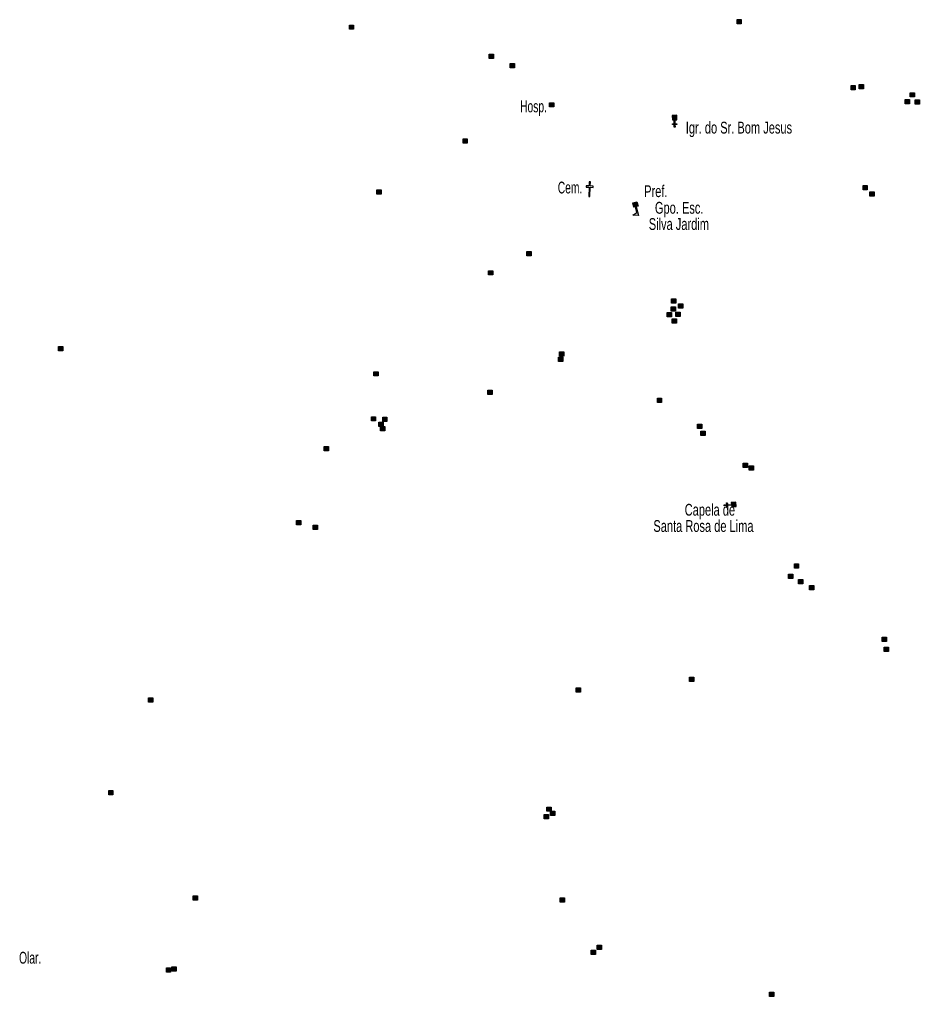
# Model space of a CAD drawing. Extents: x 647.8 to 672.9, y 6929.3 to 6957.3.
# Drawn here: x 660.13 to 666.23, y 6929.5 to 6936.12 of the extents above; entities that cross this region are included whole.
import ezdxf
from ezdxf.enums import TextEntityAlignment as Align

# ---------------------------------------------------------------- set-up
doc = ezdxf.new("R2010")
doc.units = 0
doc.header["$LTSCALE"] = 0.032
for name, color, linetype, lineweight in [('2', 7, 'Continuous', 25), ('20', 7, 'Continuous', 25), ('4', 7, 'Continuous', 25), ('6', 7, 'Continuous', 25)]:
    doc.layers.add(name, color=color, linetype=linetype, lineweight=lineweight)
doc.layers.add('61', color=7, linetype='Continuous')

msp = doc.modelspace()

# ---------------------------------------------------------------- hatches: boundary and pattern name
at = {"layer": '2'}
for points in [[(664.9931, 6936.1187), (665.0221, 6936.1187), (665.0221, 6936.0897), (664.9931, 6936.0897)], [(662.367, 6936.0814), (662.396, 6936.0814), (662.396, 6936.0524), (662.367, 6936.0524)], [(663.3148, 6935.884), (663.3438, 6935.884), (663.3438, 6935.855), (663.3148, 6935.855)], [(663.4574, 6935.8204), (663.4864, 6935.8204), (663.4864, 6935.7914), (663.4574, 6935.7914)], [(665.7653, 6935.6712), (665.7943, 6935.6712), (665.7943, 6935.6422), (665.7653, 6935.6422)], [(665.8201, 6935.6778), (665.8491, 6935.6778), (665.8491, 6935.6488), (665.8201, 6935.6488)], [(666.1317, 6935.5769), (666.1607, 6935.5769), (666.1607, 6935.5479), (666.1317, 6935.5479)], [(666.1668, 6935.6229), (666.1958, 6935.6229), (666.1958, 6935.5939), (666.1668, 6935.5939)], [(666.1997, 6935.5747), (666.2287, 6935.5747), (666.2287, 6935.5457), (666.1997, 6935.5457)], [(663.7228, 6935.5549), (663.7518, 6935.5549), (663.7518, 6935.5259), (663.7228, 6935.5259)], [(663.1371, 6935.3092), (663.1661, 6935.3092), (663.1661, 6935.2802), (663.1371, 6935.2802)], [(662.5535, 6934.9648), (662.5825, 6934.9648), (662.5825, 6934.9358), (662.5535, 6934.9358)], [(665.8465, 6934.9933), (665.8755, 6934.9933), (665.8755, 6934.9643), (665.8465, 6934.9643)], [(665.8925, 6934.9516), (665.9215, 6934.9516), (665.9215, 6934.9226), (665.8925, 6934.9226)], [(663.5693, 6934.5457), (663.5983, 6934.5457), (663.5983, 6934.5167), (663.5693, 6934.5167)], [(663.3104, 6934.4163), (663.3394, 6934.4163), (663.3394, 6934.3873), (663.3104, 6934.3873)], [(664.5477, 6934.1706), (664.5767, 6934.1706), (664.5767, 6934.1416), (664.5477, 6934.1416)], [(664.5499, 6934.2254), (664.5789, 6934.2254), (664.5789, 6934.1964), (664.5499, 6934.1964)], [(664.596, 6934.1925), (664.625, 6934.1925), (664.625, 6934.1635), (664.596, 6934.1635)], [(664.5192, 6934.1333), (664.5482, 6934.1333), (664.5482, 6934.1043), (664.5192, 6934.1043)], [(664.5784, 6934.1355), (664.6074, 6934.1355), (664.6074, 6934.1065), (664.5784, 6934.1065)], [(664.5543, 6934.0894), (664.5833, 6934.0894), (664.5833, 6934.0604), (664.5543, 6934.0604)], [(660.3969, 6933.9029), (660.4259, 6933.9029), (660.4259, 6933.8739), (660.3969, 6933.8739)], [(663.7908, 6933.8657), (663.8198, 6933.8657), (663.8198, 6933.8367), (663.7908, 6933.8367)], [(663.7842, 6933.8306), (663.8132, 6933.8306), (663.8132, 6933.8016), (663.7842, 6933.8016)], [(662.5338, 6933.7318), (662.5628, 6933.7318), (662.5628, 6933.7028), (662.5338, 6933.7028)], [(663.306, 6933.6068), (663.335, 6933.6068), (663.335, 6933.5778), (663.306, 6933.5778)], [(664.4534, 6933.5519), (664.4824, 6933.5519), (664.4824, 6933.5229), (664.4534, 6933.5229)], [(662.5162, 6933.4269), (662.5452, 6933.4269), (662.5452, 6933.3979), (662.5162, 6933.3979)], [(662.5667, 6933.3896), (662.5957, 6933.3896), (662.5957, 6933.3606), (662.5667, 6933.3606)], [(662.593, 6933.4225), (662.622, 6933.4225), (662.622, 6933.3935), (662.593, 6933.3935)], [(664.7254, 6933.3764), (664.7544, 6933.3764), (664.7544, 6933.3474), (664.7254, 6933.3474)], [(662.5776, 6933.3611), (662.6066, 6933.3611), (662.6066, 6933.3321), (662.5776, 6933.3321)], [(664.7473, 6933.3282), (664.7763, 6933.3282), (664.7763, 6933.2992), (664.7473, 6933.2992)], [(662.1959, 6933.2251), (662.2249, 6933.2251), (662.2249, 6933.1961), (662.1959, 6933.1961)], [(665.0347, 6933.111), (665.0637, 6933.111), (665.0637, 6933.082), (665.0347, 6933.082)], [(665.0764, 6933.0934), (665.1054, 6933.0934), (665.1054, 6933.0644), (665.0764, 6933.0644)], [(662.0094, 6932.7227), (662.0384, 6932.7227), (662.0384, 6932.6937), (662.0094, 6932.6937)], [(662.1213, 6932.6919), (662.1503, 6932.6919), (662.1503, 6932.6629), (662.1213, 6932.6629)], [(665.3814, 6932.4287), (665.4104, 6932.4287), (665.4104, 6932.3997), (665.3814, 6932.3997)], [(665.3419, 6932.3585), (665.3709, 6932.3585), (665.3709, 6932.3295), (665.3419, 6932.3295)], [(665.4099, 6932.3234), (665.4389, 6932.3234), (665.4389, 6932.2944), (665.4099, 6932.2944)], [(665.4845, 6932.2817), (665.5135, 6932.2817), (665.5135, 6932.2527), (665.4845, 6932.2527)], [(665.9759, 6931.9329), (666.0049, 6931.9329), (666.0049, 6931.9039), (665.9759, 6931.9039)], [(665.9891, 6931.8649), (666.0181, 6931.8649), (666.0181, 6931.8359), (665.9891, 6931.8359)], [(664.6706, 6931.6608), (664.6996, 6931.6608), (664.6996, 6931.6318), (664.6706, 6931.6318)], [(663.9027, 6931.5884), (663.9317, 6931.5884), (663.9317, 6931.5594), (663.9027, 6931.5594)], [(661.0068, 6931.5204), (661.0358, 6931.5204), (661.0358, 6931.4914), (661.0068, 6931.4914)], [(660.737, 6930.893), (660.766, 6930.893), (660.766, 6930.864), (660.737, 6930.864)], [(663.6877, 6930.7306), (663.7167, 6930.7306), (663.7167, 6930.7016), (663.6877, 6930.7016)], [(663.7053, 6930.7811), (663.7343, 6930.7811), (663.7343, 6930.7521), (663.7053, 6930.7521)], [(663.7294, 6930.7526), (663.7584, 6930.7526), (663.7584, 6930.7236), (663.7294, 6930.7236)], [(661.3096, 6930.18), (661.3386, 6930.18), (661.3386, 6930.151), (661.3096, 6930.151)], [(663.7952, 6930.1646), (663.8242, 6930.1646), (663.8242, 6930.1356), (663.7952, 6930.1356)], [(664.0058, 6929.8114), (664.0348, 6929.8114), (664.0348, 6929.7824), (664.0058, 6929.7824)], [(664.0453, 6929.8443), (664.0743, 6929.8443), (664.0743, 6929.8153), (664.0453, 6929.8153)], [(661.1275, 6929.6908), (661.1565, 6929.6908), (661.1565, 6929.6618), (661.1275, 6929.6618)], [(661.1648, 6929.6973), (661.1938, 6929.6973), (661.1938, 6929.6683), (661.1648, 6929.6683)], [(665.2124, 6929.5262), (665.2414, 6929.5262), (665.2414, 6929.4972), (665.2124, 6929.4972)]]:
    msp.add_hatch(color=256, dxfattribs=at).paths.add_polyline_path(points)
at = {"layer": '4'}
msp.add_hatch(color=256, dxfattribs=at).paths.add_polyline_path([(664.3154, 6934.8823), (664.3223, 6934.8531), (664.2932, 6934.8461), (664.2862, 6934.8753)])
at = {"layer": '6'}
for points in [[(664.5849, 6935.4399), (664.5844, 6935.4699), (664.5544, 6935.4694), (664.5549, 6935.4394)], [(664.5674, 6935.4396), (664.5724, 6935.4397), (664.5729, 6935.4122), (664.5853, 6935.4124), (664.5854, 6935.4074), (664.5729, 6935.4072), (664.5732, 6935.3897), (664.5682, 6935.3896), (664.5679, 6935.4071), (664.5554, 6935.4069), (664.5554, 6935.4119), (664.5679, 6935.4121)], [(664.9568, 6932.8154), (664.9866, 6932.8181), (664.984, 6932.8479), (664.9542, 6932.8453)], [(664.9552, 6932.8328), (664.9557, 6932.8279), (664.9282, 6932.8255), (664.9293, 6932.8131), (664.9244, 6932.8126), (664.9233, 6932.8251), (664.9058, 6932.8236), (664.9054, 6932.8285), (664.9229, 6932.83), (664.9218, 6932.8425), (664.9267, 6932.8429), (664.9278, 6932.8304)]]:
    msp.add_hatch(color=256, dxfattribs=at).paths.add_polyline_path(points)

# ---------------------------------------------------------------- linework, layer by layer
at = {"layer": '2'}
for points in [[(664.9931, 6936.1187), (665.0221, 6936.1187), (665.0221, 6936.0897), (664.9931, 6936.0897)], [(662.367, 6936.0814), (662.396, 6936.0814), (662.396, 6936.0524), (662.367, 6936.0524)], [(663.3148, 6935.884), (663.3438, 6935.884), (663.3438, 6935.855), (663.3148, 6935.855)], [(663.4574, 6935.8204), (663.4864, 6935.8204), (663.4864, 6935.7914), (663.4574, 6935.7914)], [(665.7653, 6935.6712), (665.7943, 6935.6712), (665.7943, 6935.6422), (665.7653, 6935.6422)], [(665.8201, 6935.6778), (665.8491, 6935.6778), (665.8491, 6935.6488), (665.8201, 6935.6488)], [(666.1317, 6935.5769), (666.1607, 6935.5769), (666.1607, 6935.5479), (666.1317, 6935.5479)], [(666.1668, 6935.6229), (666.1958, 6935.6229), (666.1958, 6935.5939), (666.1668, 6935.5939)], [(666.1997, 6935.5747), (666.2287, 6935.5747), (666.2287, 6935.5457), (666.1997, 6935.5457)], [(663.7228, 6935.5549), (663.7518, 6935.5549), (663.7518, 6935.5259), (663.7228, 6935.5259)], [(663.1371, 6935.3092), (663.1661, 6935.3092), (663.1661, 6935.2802), (663.1371, 6935.2802)], [(662.5535, 6934.9648), (662.5825, 6934.9648), (662.5825, 6934.9358), (662.5535, 6934.9358)], [(665.8465, 6934.9933), (665.8755, 6934.9933), (665.8755, 6934.9643), (665.8465, 6934.9643)], [(665.8925, 6934.9516), (665.9215, 6934.9516), (665.9215, 6934.9226), (665.8925, 6934.9226)], [(663.5693, 6934.5457), (663.5983, 6934.5457), (663.5983, 6934.5167), (663.5693, 6934.5167)], [(663.3104, 6934.4163), (663.3394, 6934.4163), (663.3394, 6934.3873), (663.3104, 6934.3873)], [(664.5477, 6934.1706), (664.5767, 6934.1706), (664.5767, 6934.1416), (664.5477, 6934.1416)], [(664.5499, 6934.2254), (664.5789, 6934.2254), (664.5789, 6934.1964), (664.5499, 6934.1964)], [(664.596, 6934.1925), (664.625, 6934.1925), (664.625, 6934.1635), (664.596, 6934.1635)], [(664.5192, 6934.1333), (664.5482, 6934.1333), (664.5482, 6934.1043), (664.5192, 6934.1043)], [(664.5784, 6934.1355), (664.6074, 6934.1355), (664.6074, 6934.1065), (664.5784, 6934.1065)], [(664.5543, 6934.0894), (664.5833, 6934.0894), (664.5833, 6934.0604), (664.5543, 6934.0604)], [(660.3969, 6933.9029), (660.4259, 6933.9029), (660.4259, 6933.8739), (660.3969, 6933.8739)], [(663.7908, 6933.8657), (663.8198, 6933.8657), (663.8198, 6933.8367), (663.7908, 6933.8367)], [(663.7842, 6933.8306), (663.8132, 6933.8306), (663.8132, 6933.8016), (663.7842, 6933.8016)], [(662.5338, 6933.7318), (662.5628, 6933.7318), (662.5628, 6933.7028), (662.5338, 6933.7028)], [(663.306, 6933.6068), (663.335, 6933.6068), (663.335, 6933.5778), (663.306, 6933.5778)], [(664.4534, 6933.5519), (664.4824, 6933.5519), (664.4824, 6933.5229), (664.4534, 6933.5229)], [(662.5162, 6933.4269), (662.5452, 6933.4269), (662.5452, 6933.3979), (662.5162, 6933.3979)], [(662.5667, 6933.3896), (662.5957, 6933.3896), (662.5957, 6933.3606), (662.5667, 6933.3606)], [(662.593, 6933.4225), (662.622, 6933.4225), (662.622, 6933.3935), (662.593, 6933.3935)], [(664.7254, 6933.3764), (664.7544, 6933.3764), (664.7544, 6933.3474), (664.7254, 6933.3474)], [(662.5776, 6933.3611), (662.6066, 6933.3611), (662.6066, 6933.3321), (662.5776, 6933.3321)], [(664.7473, 6933.3282), (664.7763, 6933.3282), (664.7763, 6933.2992), (664.7473, 6933.2992)], [(662.1959, 6933.2251), (662.2249, 6933.2251), (662.2249, 6933.1961), (662.1959, 6933.1961)], [(665.0347, 6933.111), (665.0637, 6933.111), (665.0637, 6933.082), (665.0347, 6933.082)], [(665.0764, 6933.0934), (665.1054, 6933.0934), (665.1054, 6933.0644), (665.0764, 6933.0644)], [(662.0094, 6932.7227), (662.0384, 6932.7227), (662.0384, 6932.6937), (662.0094, 6932.6937)], [(662.1213, 6932.6919), (662.1503, 6932.6919), (662.1503, 6932.6629), (662.1213, 6932.6629)], [(665.3814, 6932.4287), (665.4104, 6932.4287), (665.4104, 6932.3997), (665.3814, 6932.3997)], [(665.3419, 6932.3585), (665.3709, 6932.3585), (665.3709, 6932.3295), (665.3419, 6932.3295)], [(665.4099, 6932.3234), (665.4389, 6932.3234), (665.4389, 6932.2944), (665.4099, 6932.2944)], [(665.4845, 6932.2817), (665.5135, 6932.2817), (665.5135, 6932.2527), (665.4845, 6932.2527)], [(665.9759, 6931.9329), (666.0049, 6931.9329), (666.0049, 6931.9039), (665.9759, 6931.9039)], [(665.9891, 6931.8649), (666.0181, 6931.8649), (666.0181, 6931.8359), (665.9891, 6931.8359)], [(664.6706, 6931.6608), (664.6996, 6931.6608), (664.6996, 6931.6318), (664.6706, 6931.6318)], [(663.9027, 6931.5884), (663.9317, 6931.5884), (663.9317, 6931.5594), (663.9027, 6931.5594)], [(661.0068, 6931.5204), (661.0358, 6931.5204), (661.0358, 6931.4914), (661.0068, 6931.4914)], [(660.737, 6930.893), (660.766, 6930.893), (660.766, 6930.864), (660.737, 6930.864)], [(663.6877, 6930.7306), (663.7167, 6930.7306), (663.7167, 6930.7016), (663.6877, 6930.7016)], [(663.7053, 6930.7811), (663.7343, 6930.7811), (663.7343, 6930.7521), (663.7053, 6930.7521)], [(663.7294, 6930.7526), (663.7584, 6930.7526), (663.7584, 6930.7236), (663.7294, 6930.7236)], [(661.3096, 6930.18), (661.3386, 6930.18), (661.3386, 6930.151), (661.3096, 6930.151)], [(663.7952, 6930.1646), (663.8242, 6930.1646), (663.8242, 6930.1356), (663.7952, 6930.1356)], [(664.0058, 6929.8114), (664.0348, 6929.8114), (664.0348, 6929.7824), (664.0058, 6929.7824)], [(664.0453, 6929.8443), (664.0743, 6929.8443), (664.0743, 6929.8153), (664.0453, 6929.8153)], [(661.1275, 6929.6908), (661.1565, 6929.6908), (661.1565, 6929.6618), (661.1275, 6929.6618)], [(661.1648, 6929.6973), (661.1938, 6929.6973), (661.1938, 6929.6683), (661.1648, 6929.6683)], [(665.2124, 6929.5262), (665.2414, 6929.5262), (665.2414, 6929.4972), (665.2124, 6929.4972)]]:
    msp.add_lwpolyline(points, close=True, dxfattribs=at)
at = {"layer": '20'}
for points in [[(663.9909, 6934.9908), (663.9709, 6934.9914), (663.9707, 6934.9829), (663.9906, 6934.9823), (663.9887, 6934.9188)], [(663.9887, 6934.9188), (663.9967, 6934.9186), (663.9986, 6934.9821)], [(663.9989, 6934.9906), (663.9998, 6935.0185), (663.9918, 6935.0188), (663.9909, 6934.9908)], [(663.9986, 6934.9821), (664.0186, 6934.9814), (664.0189, 6934.9899), (663.9989, 6934.9906)]]:
    msp.add_lwpolyline(points, dxfattribs=at)
at = {"layer": '4'}
msp.add_line((664.3102, 6934.8502), (664.3053, 6934.849), dxfattribs=at)
for points in [[(664.3154, 6934.8823), (664.3223, 6934.8531), (664.2932, 6934.8461), (664.2862, 6934.8753)], [(664.3102, 6934.8502), (664.3247, 6934.7894), (664.2878, 6934.7934), (664.3145, 6934.8106), (664.3053, 6934.849)]]:
    msp.add_lwpolyline(points, close=True, dxfattribs=at)
at = {"layer": '6'}
for points in [[(664.5849, 6935.4399), (664.5844, 6935.4699), (664.5544, 6935.4694), (664.5549, 6935.4394)], [(664.5674, 6935.4396), (664.5724, 6935.4397), (664.5729, 6935.4122), (664.5853, 6935.4124), (664.5854, 6935.4074), (664.5729, 6935.4072), (664.5732, 6935.3897), (664.5682, 6935.3896), (664.5679, 6935.4071), (664.5554, 6935.4069), (664.5554, 6935.4119), (664.5679, 6935.4121)], [(664.9568, 6932.8154), (664.9866, 6932.8181), (664.984, 6932.8479), (664.9542, 6932.8453)], [(664.9552, 6932.8328), (664.9557, 6932.8279), (664.9282, 6932.8255), (664.9293, 6932.8131), (664.9244, 6932.8126), (664.9233, 6932.8251), (664.9058, 6932.8236), (664.9054, 6932.8285), (664.9229, 6932.83), (664.9218, 6932.8425), (664.9267, 6932.8429), (664.9278, 6932.8304)]]:
    msp.add_lwpolyline(points, close=True, dxfattribs=at)

# ---------------------------------------------------------------- texts
at = {"layer": '61'}
for s, width, p in [('Hosp.', 0.65, (663.7052, 6935.49)), ('Cem.', 0.65, (663.945, 6934.94)), ('      Capela de      ', 0.7, (665.1048, 6932.7559)), ('Santa Rosa de Lima', 0.7, (665.1048, 6932.6459))]:
    msp.add_text(s, height=0.08, dxfattribs=dict(at, width=width)).set_placement(p, align=Align.RIGHT)
for s, width, p in [('Igr. do Sr. Bom Jesus', 0.7, (664.6461, 6935.346)), ('Pref.', 0.7, (664.364, 6934.9151)), ('  Gpo. Esc.', 0.7, (664.3952, 6934.8026)), ('Silva Jardim', 0.7, (664.3952, 6934.6926)), ('Olar.', 0.65, (660.1299, 6929.7195))]:
    msp.add_text(s, height=0.08, dxfattribs=dict(at, width=width)).set_placement(p)

doc.saveas('drawing.dxf')
